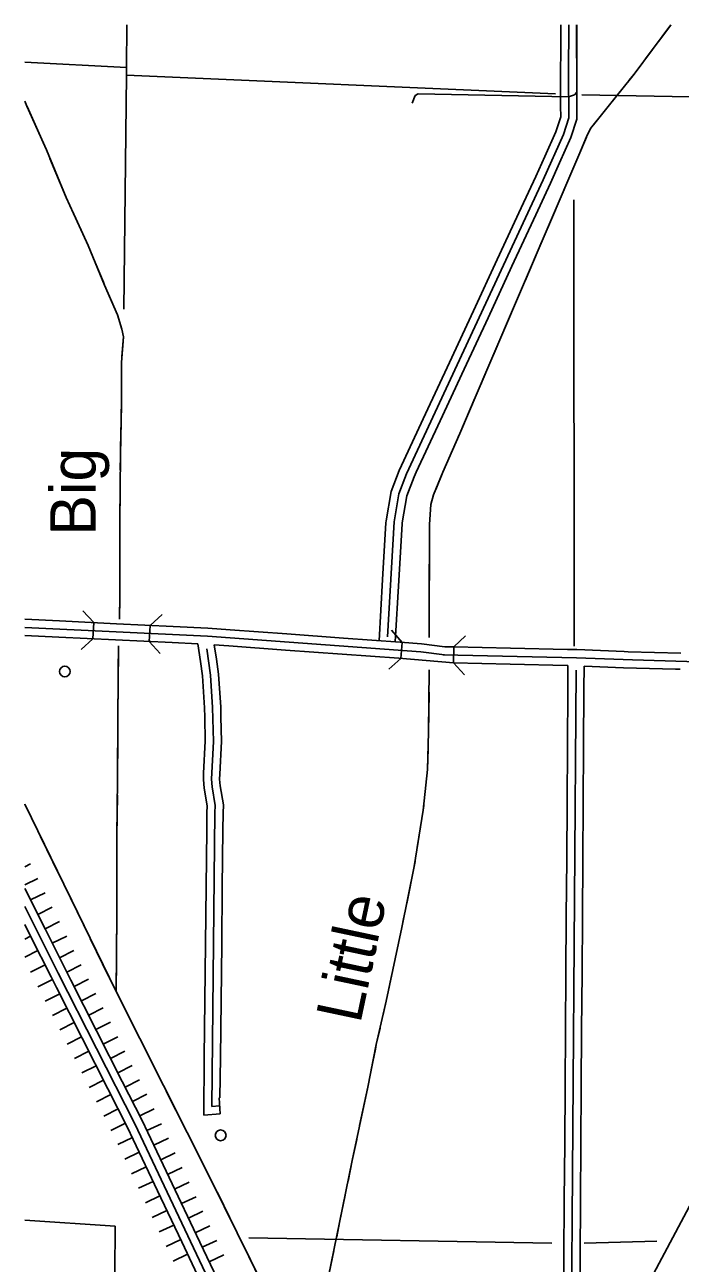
# Model space of a CAD drawing. Extents: x -4306 to 3843, y 131 to 8053.
# Drawn here: x -2796 to -1822, y 6210 to 8053 of the extents above; entities that cross this region are included whole.
import ezdxf

# ---------------------------------------------------------------- set-up
doc = ezdxf.new("R2010")
doc.units = 0
for name, color, linetype in [('29', 7, 'Continuous'), ('32', 7, 'Continuous'), ('38', 7, 'Continuous'), ('4', 7, 'Continuous'), ('43', 7, 'Continuous'), ('45', 7, 'Continuous'), ('5', 7, 'Continuous'), ('56', 7, 'Continuous'), ('7', 7, 'Continuous')]:
    doc.layers.add(name, color=color, linetype=linetype)

msp = doc.modelspace()

# ---------------------------------------------------------------- linework, layer by layer
at = {"layer": '29'}
for p, q in [((-2787.5, 6804.4), (-2796.1, 6800.1)), ((-2776.8, 6783), (-2796.1, 6773.3)), ((-2776.8, 6783), (-2796.1, 6773.3)), ((-2766, 6761.5), (-2787.5, 6750.8)), ((-2755.2, 6740.1), (-2776.7, 6729.3)), ((-2744.5, 6718.6), (-2765.9, 6707.9)), ((-2744.5, 6718.6), (-2765.9, 6707.9)), ((-2787.4, 6697.1), (-2796.1, 6692.7)), ((-2787.4, 6697.1), (-2796.1, 6692.7)), ((-2733.7, 6697.2), (-2755.2, 6686.4)), ((-2776.6, 6675.6), (-2796.1, 6665.9)), ((-2723, 6675.7), (-2744.4, 6664.9)), ((-2765.9, 6654.2), (-2787.4, 6643.4)), ((-2712.3, 6654.4), (-2733.7, 6643.5)), ((-2712.3, 6654.4), (-2733.7, 6643.5)), ((-2755.1, 6632.7), (-2776.5, 6621.8)), ((-2755.1, 6632.7), (-2776.5, 6621.8)), ((-2701.4, 6633), (-2722.8, 6622.1)), ((-2744.2, 6611.3), (-2765.6, 6600.4)), ((-2690.6, 6611.6), (-2712, 6600.7)), ((-2733.4, 6589.9), (-2754.8, 6579)), ((-2679.7, 6590.2), (-2701.1, 6579.3)), ((-2679.7, 6590.2), (-2701.1, 6579.3)), ((-2722.5, 6568.5), (-2743.9, 6557.6)), ((-2722.5, 6568.5), (-2743.9, 6557.6)), ((-2668.9, 6568.8), (-2690.3, 6557.9)), ((-2711.7, 6547.1), (-2733.1, 6536.2)), ((-2658, 6547.4), (-2679.4, 6536.5)), ((-2700.8, 6525.7), (-2722.2, 6514.8)), ((-2647.2, 6525.9), (-2668.6, 6515.1)), ((-2647.2, 6525.9), (-2668.6, 6515.1)), ((-2636.3, 6504.5), (-2657.7, 6493.7)), ((-2690, 6504.2), (-2711.4, 6493.4)), ((-2690, 6504.2), (-2711.4, 6493.4)), ((-2679.1, 6482.8), (-2700.5, 6472)), ((-2625.4, 6483.1), (-2646.9, 6472.3)), ((-2668.3, 6461.4), (-2689.7, 6450.6)), ((-2614.6, 6461.7), (-2636, 6450.9)), ((-2614.6, 6461.7), (-2636, 6450.9)), ((-2657.4, 6440), (-2678.8, 6429.2)), ((-2657.4, 6440), (-2678.8, 6429.2)), ((-2603.7, 6440.3), (-2625.1, 6429.5)), ((-2646.6, 6418.6), (-2668, 6407.8)), ((-2592.9, 6417.9), (-2614.6, 6407.6)), ((-2636.2, 6397.3), (-2657.9, 6387)), ((-2582.6, 6396.2), (-2604.3, 6385.9)), ((-2582.6, 6396.2), (-2604.3, 6385.9)), ((-2626, 6375.6), (-2647.6, 6365.3)), ((-2626, 6375.6), (-2647.6, 6365.3)), ((-2572.3, 6374.5), (-2594, 6364.2)), ((-2615.7, 6353.9), (-2637.4, 6343.6)), ((-2562, 6352.8), (-2583.7, 6342.5)), ((-2605.4, 6332.2), (-2627.1, 6321.9)), ((-2551.7, 6331.1), (-2573.4, 6320.8)), ((-2551.7, 6331.1), (-2573.4, 6320.8)), ((-2595.1, 6310.5), (-2616.8, 6300.3)), ((-2595.1, 6310.5), (-2616.8, 6300.3)), ((-2541.4, 6309.4), (-2563.1, 6299.1)), ((-2584.8, 6288.9), (-2606.5, 6278.6)), ((-2531.2, 6287.7), (-2552.8, 6277.4)), ((-2574.5, 6267.2), (-2596.2, 6256.9)), ((-2520.9, 6266), (-2542.6, 6255.8)), ((-2520.9, 6266), (-2542.6, 6255.8)), ((-2564.2, 6245.5), (-2585.9, 6235.2)), ((-2564.2, 6245.5), (-2585.9, 6235.2)), ((-2510.6, 6244.4), (-2532.3, 6234.1)), ((-2554, 6223.8), (-2575.6, 6213.5)), ((-2500.3, 6222.7), (-2522, 6212.4))]:
    msp.add_line(p, q, dxfattribs=at)
at = {"layer": '32'}
for p, q in [((-1976, 8053), (-1975.2, 7952.9)), ((-2215.8, 7947.6), (-2220.1, 7936.1)), ((-2211.3, 7950.1), (-2215.8, 7947.6)), ((-1987.8, 7945.7), (-2211.3, 7950.1)), ((-1978.8, 7948.5), (-1987.8, 7945.7)), ((-1975.2, 7952.9), (-1978.8, 7948.5)), ((-2744.4, 7165.9), (-2796.1, 7168.4)), ((-2524.5, 7143.3), (-2796.1, 7156.4)), ((-2660, 7161.8), (-2744.4, 7165.9)), ((-2694.7, 7139.5), (-2693.6, 7163.4)), ((-2575.6, 7157.8), (-2660, 7161.8)), ((-2611, 7135.4), (-2609.8, 7159.4)), ((-2523.8, 7155.3), (-2575.6, 7157.8)), ((-2491, 7152.9), (-2523.8, 7155.3)), ((-2406.7, 7146.7), (-2491, 7152.9)), ((-2745.6, 7141.9), (-2796.1, 7144.4)), ((-2661.2, 7137.9), (-2745.6, 7141.9)), ((-2576.8, 7133.8), (-2661.2, 7137.9)), ((-2538.9, 7132), (-2576.8, 7133.8)), ((-2207.5, 7120), (-2524.5, 7143.3)), ((-2322.5, 7140.5), (-2406.7, 7146.7)), ((-2238.2, 7134.3), (-2322.5, 7140.5)), ((-2206.3, 7131.9), (-2238.2, 7134.3)), ((-2237, 7110.1), (-2235.2, 7134.1)), ((-2171.4, 7127.6), (-2206.3, 7131.9)), ((-2520, 7085.4), (-2525.7, 7124.6)), ((-2492.7, 7128.9), (-2514.4, 7130.5)), ((-2408.5, 7122.7), (-2492.7, 7128.9)), ((-2324.2, 7116.5), (-2408.5, 7122.7)), ((-2239.9, 7110.4), (-2324.2, 7116.5)), ((-2172.2, 7115.7), (-2207.5, 7120)), ((-1976, 7111.3), (-2174.1, 7115.7)), ((-2158.4, 7127.4), (-2171.4, 7127.6)), ((-2158.4, 7127.4), (-2158.9, 7103.4)), ((-2073.9, 7125.5), (-2158.4, 7127.4)), ((-1989.5, 7123.6), (-2073.9, 7125.5)), ((-1975.6, 7123.3), (-1989.5, 7123.6)), ((-1904.8, 7120.4), (-1975.6, 7123.3)), ((-1899.3, 7120.2), (-1904.8, 7120.4)), ((-1821, 7118), (-1899.3, 7120.2)), ((-2158.9, 7103.4), (-2239.9, 7110.4)), ((-2074.5, 7101.5), (-2158.9, 7103.4)), ((-1990, 7099.6), (-2074.5, 7101.5)), ((-1988.6, 7099.6), (-1990, 7099.6)), ((-1988.8, 7064.5), (-1988.6, 7099.6)), ((-1892.6, 7107.9), (-1976, 7111.3)), ((-1964.8, 7064.4), (-1964.6, 7098.8)), ((-1905.8, 7096.4), (-1964.6, 7098.8)), ((-1828.6, 7094.2), (-1905.8, 7096.4)), ((-1568, 7099), (-1892.8, 7108)), ((-1821.7, 7094), (-1828.6, 7094.2)), ((-2516.8, 7037.1), (-2520, 7085.4)), ((-1989.4, 6980), (-1988.8, 7064.5)), ((-1965.4, 6979.9), (-1964.8, 7064.4)), ((-2515.7, 6986.7), (-2516.8, 7037.1)), ((-2518.6, 6930.6), (-2515.7, 6986.7)), ((-1990, 6895.6), (-1989.4, 6980)), ((-1966, 6895.4), (-1965.4, 6979.9)), ((-2517.4, 6919), (-2518.6, 6930.6)), ((-2513, 6891.6), (-2517.4, 6919)), ((-2513.4, 6880.4), (-2513, 6891.6)), ((-1990.5, 6811.1), (-1990, 6895.6)), ((-1966.5, 6810.9), (-1966, 6895.4)), ((-2518, 6443.7), (-2513.4, 6880.4)), ((-1991.1, 6726.6), (-1990.5, 6811.1)), ((-1967.1, 6726.4), (-1966.5, 6810.9)), ((-2765.5, 6707), (-2796.1, 6768)), ((-2746.4, 6642.1), (-2796.1, 6741.2)), ((-2746.4, 6642.1), (-2796.1, 6741.2)), ((-1991.7, 6642.1), (-1991.1, 6726.6)), ((-1967.7, 6641.9), (-1967.1, 6726.4)), ((-2787, 6696.2), (-2796.1, 6714.5)), ((-2735.7, 6647.5), (-2765.5, 6707)), ((-2757.1, 6636.7), (-2787, 6696.2)), ((-2749, 6620.7), (-2757.1, 6636.7)), ((-2632.6, 6417.6), (-2746.4, 6642.1)), ((-2632.6, 6417.6), (-2746.4, 6642.1)), ((-2727.6, 6631.6), (-2735.7, 6647.5)), ((-1992.3, 6557.6), (-1991.7, 6642.1)), ((-1968.3, 6557.4), (-1967.7, 6641.9)), ((-2710.8, 6545.3), (-2749, 6620.7)), ((-2689.4, 6556.2), (-2727.6, 6631.6)), ((-2672.6, 6470), (-2710.8, 6545.3)), ((-2651.2, 6480.8), (-2689.4, 6556.2)), ((-1992.9, 6473.1), (-1992.3, 6557.6)), ((-1968.9, 6473), (-1968.3, 6557.4)), ((-2643.4, 6412.3), (-2672.6, 6470)), ((-2621.8, 6422.9), (-2651.2, 6480.8)), ((-1993.4, 6388.6), (-1992.9, 6473.1)), ((-1969.4, 6388.5), (-1968.9, 6473)), ((-2506.5, 6444.6), (-2518, 6443.7)), ((-2635, 6394.7), (-2643.4, 6412.3)), ((-2486.1, 6108.6), (-2632.6, 6417.6)), ((-2486.1, 6108.6), (-2632.6, 6417.6)), ((-2613.3, 6405), (-2621.8, 6422.9)), ((-2598.8, 6318.3), (-2635, 6394.7)), ((-2577.1, 6328.6), (-2613.3, 6405)), ((-1994, 6304.2), (-1993.4, 6388.6)), ((-1970, 6304), (-1969.4, 6388.5)), ((-2540.9, 6252.3), (-2577.1, 6328.6)), ((-2562.6, 6242), (-2598.8, 6318.3)), ((-1994.6, 6219.7), (-1994, 6304.2)), ((-1970.6, 6219.5), (-1970, 6304)), ((-2504.7, 6176), (-2540.9, 6252.3)), ((-2526.4, 6165.7), (-2562.6, 6242)), ((-1995.2, 6135.2), (-1994.6, 6219.7)), ((-1971.2, 6135), (-1970.6, 6219.5))]:
    msp.add_line(p, q, dxfattribs=at)
msp.add_lwpolyline([(-1983.6, 6071.9), (-1976.6, 7092.7)], dxfattribs=at)
at = {"layer": '38'}
for p, q in [((-2694.2, 7151.5), (-2694.2, 7151.5)), ((-2610.4, 7147.4), (-2610.4, 7147.4)), ((-2141.1, 7143.9), (-2158.4, 7127.4)), ((-2236.1, 7122.1), (-2236.1, 7122.1)), ((-2158.9, 7103.4), (-2142.4, 7086))]:
    msp.add_line(p, q, dxfattribs=at)
for points in [[(-2693.6, 7163.4), (-2709.7, 7181.2)], [(-2592.1, 7175.5), (-2609.8, 7159.4)], [(-2235.2, 7134), (-2250.9, 7152.2)], [(-2712.5, 7123.3), (-2694.7, 7139.5)], [(-2611, 7135.4), (-2594.9, 7117.7)], [(-2255.1, 7094.4), (-2237, 7110.1)]]:
    msp.add_lwpolyline(points, dxfattribs=at)
at = {"layer": '4'}
for p, q in [((-2645, 7989.6), (-2644.4, 8053)), ((-2645.1, 7977.8), (-2645, 7989.6)), ((-2648.9, 7629.7), (-2645.1, 7977.8))]:
    msp.add_line(p, q, dxfattribs=at)
at = {"layer": '43'}
for points in [[(-1835.5, 8053), (-1890.1, 7979.7)], [(-1835.8, 8052.6), (-1873.6, 8001.8)], [(-2106.1, 7545.8), (-1972.4, 7859.1), (-1960.9, 7886), (-1955, 7898.7), (-1890.1, 7979.7)], [(-1897.9, 7970), (-1890.1, 7979.7)], [(-1886.3, 7984.8), (-1890.1, 7979.7)], [(-1950.8, 7904.1), (-1911.1, 7953.5)], [(-2655.3, 7168.6), (-2654.9, 7205.3), (-2654.9, 7311.2), (-2654, 7412.9), (-2652.3, 7487.4), (-2652.3, 7550.5), (-2649.4, 7588.7), (-2651.6, 7600), (-2658.3, 7621.4), (-2677.5, 7665.7), (-2701.8, 7724.3), (-2734.6, 7796.1), (-2764, 7866.7), (-2793.1, 7931.9), (-2796.1, 7939.4)], [(-2767, 7873.5), (-2792.8, 7931.4)], [(-1985.9, 7827.5), (-1972.4, 7859.1), (-1961, 7885.8)], [(-2734.4, 7795.6), (-2734.6, 7796.1), (-2758.8, 7854.1)], [(-2019.1, 7749.8), (-1994.2, 7808.1)], [(-2699.5, 7718.6), (-2701.8, 7724.3), (-2725.6, 7776.4)], [(-2052.3, 7672.1), (-2027.4, 7730.4)], [(-2679.2, 7669.9), (-2691.4, 7699.1)], [(-2666.7, 7640.8), (-2677.5, 7665.7), (-2679.2, 7669.9)], [(-2085.4, 7594.4), (-2060.5, 7652.6)], [(-2651.6, 7559.3), (-2649.4, 7588.7), (-2651.6, 7600), (-2658.3, 7621.4)], [(-2106.1, 7545.8), (-2093.7, 7574.9)], [(-2652.6, 7474.9), (-2652.3, 7487.4), (-2652.3, 7538.2)], [(-2194.8, 7141.1), (-2194.8, 7192.4), (-2194.2, 7309.4), (-2192.5, 7339.1), (-2188.7, 7353.5), (-2174.4, 7387.4), (-2149.3, 7444.6), (-2109.3, 7539.1), (-2106.1, 7545.8)], [(-2118.7, 7516.9), (-2109.3, 7539.1), (-2106.1, 7545.8)], [(-2151.7, 7439.2), (-2149.3, 7444.6), (-2126.9, 7497.5)], [(-2654.2, 7390.4), (-2654, 7412.9), (-2653.1, 7453.8)], [(-2185.2, 7361.6), (-2174.4, 7387.4), (-2160.2, 7419.8)], [(-2654.9, 7305.9), (-2654.9, 7311.2), (-2654.3, 7369.3)], [(-2194.4, 7278.4), (-2194.2, 7309.4), (-2192.5, 7339.1), (-2191.8, 7341.6)], [(-2654.9, 7221.4), (-2654.9, 7284.8)], [(-2194.8, 7193.9), (-2194.5, 7257.3)], [(-2655.3, 7168.6), (-2655, 7200.3)], [(-2194.8, 7141.1), (-2194.8, 7172.8)], [(-2656.6, 7128.8), (-2657, 7122.3), (-2657.7, 7024.7), (-2658.2, 6930), (-2659.3, 6846), (-2659.3, 6727.2), (-2660.4, 6614.7)], [(-2656.6, 7128.8), (-2657, 7122.3), (-2657.2, 7097.1)], [(-2657.3, 7076), (-2657.7, 7024.7), (-2657.7, 7012.6)], [(-2392.7, 6038.1), (-2378.6, 6062.3), (-2369.7, 6077.6), (-2364.9, 6097), (-2348.4, 6171.8), (-2328.1, 6270.9), (-2309.3, 6363), (-2286.2, 6472.4), (-2273.5, 6535.7), (-2258.9, 6600.2), (-2235.6, 6710), (-2217.1, 6800.5), (-2203.6, 6884.4), (-2197.5, 6944.9), (-2195.7, 7000.5), (-2194.8, 7093.4)], [(-2195.4, 7028.4), (-2195.1, 7060)], [(-1330.4, 7050.5), (-1406.5, 6952.3), (-1451.4, 6892.2), (-1538.8, 6762.8), (-1606.3, 6643.7), (-1713.9, 6460.4), (-1775.4, 6357), (-1861.2, 6194.6), (-1921.7, 6085.7), (-1963.4, 6016.6), (-2014.8, 5943)], [(-2195.9, 6996.7), (-2195.7, 7000.5), (-2195.4, 7028.4)], [(-2657.9, 6991.5), (-2658.2, 6930), (-2658.3, 6928.2)], [(-2200.8, 6912.4), (-2197.5, 6944.9), (-2196.5, 6975.6)], [(-2796.1, 6893.3), (-2660.3, 6614.6), (-2519.4, 6334.9), (-2401.8, 6095.8), (-2395, 6040.1)], [(-2796.1, 6893.3), (-2795.8, 6892.7)], [(-2795.8, 6892.7), (-2781.9, 6864.2)], [(-2658.5, 6907), (-2659.3, 6846), (-2659.3, 6843.7)], [(-2212.6, 6828.8), (-2203.6, 6884.4), (-2202.9, 6891.4)], [(-2772.7, 6845.3), (-2745, 6788.3)], [(-2659.3, 6822.6), (-2659.3, 6759.2)], [(-2228.3, 6745.8), (-2217.1, 6800.5), (-2215.9, 6807.9)], [(-2735.7, 6769.3), (-2708, 6712.3)], [(-2659.3, 6738.1), (-2659.3, 6727.2), (-2659.8, 6674.7)], [(-2245.6, 6663.1), (-2235.6, 6710), (-2232.5, 6725.1)], [(-2698.7, 6693.3), (-2671, 6636.4)], [(-2660, 6653.6), (-2660.3, 6621.9)], [(-2263.4, 6580.5), (-2258.9, 6600.2), (-2250, 6642.4)], [(-2661.7, 6617.4), (-2660.3, 6614.6), (-2633.2, 6560.8)], [(-2660.3, 6621.9), (-2660.4, 6614.7)], [(-2274.8, 6528.9), (-2273.5, 6535.7), (-2268, 6559.9)], [(-2623.7, 6541.9), (-2595.2, 6485.3)], [(-2281.1, 6497.9), (-2274.8, 6528.9)], [(-2298.3, 6415.1), (-2286.2, 6472.4), (-2285.3, 6477.2)], [(-2585.7, 6466.5), (-2571.4, 6438.2)], [(-2571.4, 6438.2), (-2557.2, 6409.9)], [(-2315.5, 6332.4), (-2309.3, 6363), (-2302.6, 6394.5)], [(-2547.7, 6391), (-2519.4, 6334.9), (-2519.2, 6334.4)], [(-2509.8, 6315.5), (-2481.9, 6258.6)], [(-2332.4, 6249.6), (-2328.1, 6270.9), (-2319.7, 6311.7)], [(-2472.5, 6239.7), (-2444.6, 6182.8)], [(-2349.5, 6166.9), (-2348.4, 6171.8), (-2336.7, 6229)]]:
    msp.add_lwpolyline(points, dxfattribs=at)
at = {"layer": '45'}
for p, q in [((-1999.4, 8016.5), (-1999.3, 8053)), ((-1987.6, 7979.9), (-1987.3, 8053)), ((-1975.4, 8016.3), (-1975.3, 8053)), ((-1999.6, 7979.9), (-1999.4, 8016.5)), ((-1975.6, 7979.9), (-1975.4, 8016.3)), ((-1999.5, 7931.9), (-1999.6, 7979.9)), ((-1987.4, 7914.3), (-1987.6, 7979.9)), ((-1975.5, 7931.9), (-1975.6, 7979.9)), ((-1999.4, 7916.2), (-1999.5, 7931.9)), ((-1975.4, 7912.4), (-1975.5, 7931.9)), ((-2006.6, 7893.8), (-1999.4, 7916.2)), ((-1995.4, 7889.5), (-1987.4, 7914.3)), ((-1984.1, 7885.2), (-1975.4, 7912.4)), ((-2025.5, 7822), (-1995.4, 7889.5)), ((-2023, 7857.1), (-2006.6, 7893.8)), ((-2001.1, 7847.3), (-1984.1, 7885.2)), ((-2036.5, 7827), (-2023, 7857.1)), ((-2014.6, 7817.1), (-2001.1, 7847.3)), ((-2228.4, 7384.9), (-2025.5, 7822)), ((-2058.1, 7780.4), (-2036.5, 7827)), ((-2036.3, 7770.3), (-2014.6, 7817.1)), ((-2093.6, 7703.8), (-2058.1, 7780.4)), ((-2071.9, 7693.7), (-2036.3, 7770.3)), ((-2129.2, 7627.2), (-2093.6, 7703.8)), ((-2107.4, 7617.1), (-2071.9, 7693.7)), ((-2164.8, 7550.5), (-2129.2, 7627.2)), ((-2143, 7540.4), (-2107.4, 7617.1)), ((-2200.3, 7473.9), (-2164.8, 7550.5)), ((-2178.6, 7463.8), (-2143, 7540.4)), ((-2235.9, 7397.3), (-2200.3, 7473.9)), ((-2214.1, 7387.2), (-2178.6, 7463.8)), ((-2251.6, 7358.4), (-2239.5, 7389.6)), ((-2239.5, 7389.6), (-2235.9, 7397.3)), ((-2240, 7355.2), (-2228.4, 7384.9)), ((-2228.3, 7352), (-2217.4, 7380.2)), ((-2217.4, 7380.2), (-2214.1, 7387.2)), ((-2259, 7314.9), (-2251.6, 7358.4)), ((-2247, 7313.5), (-2240, 7355.2)), ((-2235.1, 7312.1), (-2228.3, 7352)), ((-2264.1, 7227.6), (-2259.2, 7311.9)), ((-2259.2, 7311.9), (-2259, 7314.9)), ((-2257.1, 7142.5), (-2247, 7313.5)), ((-2240.1, 7226.2), (-2235.2, 7310.5)), ((-2235.2, 7310.5), (-2235.1, 7312.1)), ((-2269.5, 7136.6), (-2264.1, 7227.6)), ((-2245.5, 7134.8), (-2240.1, 7226.2)), ((-2535.1, 7105.5), (-2538.9, 7132)), ((-2511.3, 7108.9), (-2514.4, 7130.5)), ((-2532, 7084.1), (-2535.1, 7105.5)), ((-2508.1, 7086.6), (-2511.3, 7108.9)), ((-2528.7, 7036.6), (-2532, 7084.1)), ((-2504.8, 7037.7), (-2508.1, 7086.6)), ((-2528.5, 7022.8), (-2528.7, 7036.6)), ((-2527.7, 6986.9), (-2528.5, 7022.8)), ((-2504.5, 7023.3), (-2504.8, 7037.7)), ((-2503.7, 6986.5), (-2504.5, 7023.3)), ((-2530.2, 6939.3), (-2527.7, 6986.9)), ((-2506.2, 6938), (-2503.7, 6986.5)), ((-2530.6, 6930.3), (-2530.2, 6939.3)), ((-2529.3, 6917.4), (-2530.6, 6930.3)), ((-2506.6, 6930.8), (-2506.2, 6938)), ((-2505.5, 6920.6), (-2506.6, 6930.8)), ((-2525, 6890.9), (-2529.3, 6917.4)), ((-2500.9, 6892.4), (-2505.5, 6920.6)), ((-2501.4, 6880.1), (-2500.9, 6892.4)), ((-2525.7, 6854.7), (-2525.4, 6880.7)), ((-2525.4, 6880.7), (-2525, 6890.9)), ((-2501.7, 6854.5), (-2501.4, 6880.1)), ((-2526.6, 6770.3), (-2525.7, 6854.7)), ((-2502.6, 6770), (-2501.7, 6854.5)), ((-2527.5, 6685.8), (-2526.6, 6770.3)), ((-2503.4, 6685.5), (-2502.6, 6770)), ((-2528.3, 6601.3), (-2527.5, 6685.8)), ((-2504.3, 6601), (-2503.4, 6685.5)), ((-2529.2, 6516.8), (-2528.3, 6601.3)), ((-2505.2, 6516.5), (-2504.3, 6601)), ((-2530.1, 6430.8), (-2529.2, 6516.8)), ((-2505.9, 6456.6), (-2505.2, 6516.5)), ((-2507.3, 6456.5), (-2505.6, 6432.6)), ((-2505.6, 6432.6), (-2530.1, 6430.8))]:
    msp.add_line(p, q, dxfattribs=at)
at = {"layer": '5'}
for p, q in [((-2645, 7989.6), (-2796.1, 7997.5)), ((-2007, 7950.1), (-2645.1, 7977.8)), ((-1703.8, 7943.7), (-1968.1, 7948.7)), ((-1979.5, 7128.3), (-1979.7, 7792.7)), ((-2012.6, 6240.1), (-2463.1, 6248)), ((-1856.6, 6243.4), (-1964.4, 6240.1))]:
    msp.add_line(p, q, dxfattribs=at)
at = {"layer": '56'}
for centre in [(-2736.6, 7090.7), (-2504.9, 6400.6)]:
    msp.add_circle(centre, 8, dxfattribs=at)
at = {"layer": '7'}
for p, q in [((-2796.1, 6274.2), (-2661.8, 6265.3)), ((-2661.8, 6265.3), (-2661.9, 6251.5)), ((-2661.9, 6251.5), (-2664.4, 6055.5))]:
    msp.add_line(p, q, dxfattribs=at)

# ---------------------------------------------------------------- texts
at = {"layer": '43'}
for s, rotation, p in [('Big', 89.818, (-2690.8, 7292.9)), ('Little', 78.0382, (-2297.4, 6565.4))]:
    msp.add_text(s, height=67.59, rotation=rotation, dxfattribs=at).set_placement(p)

doc.saveas('drawing.dxf')
